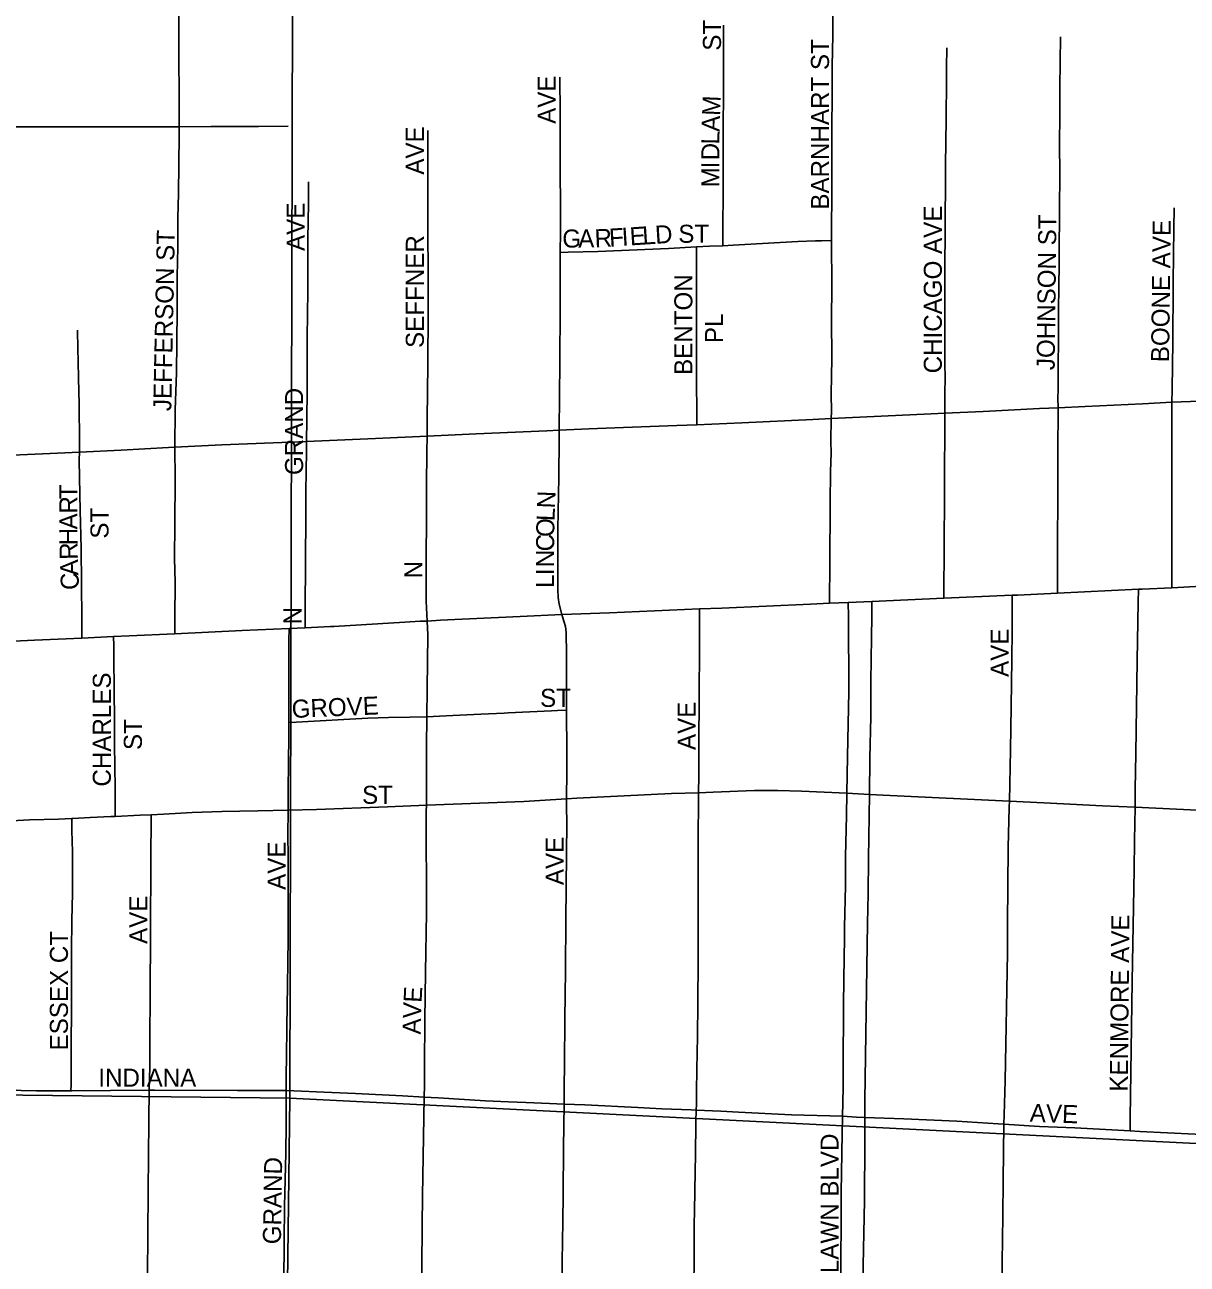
# Model space of a CAD drawing. Extents: x -9.1 to 34, y -3.1 to 22.
# Drawn here: x 6.099 to 6.709, y 19.674 to 20.324 of the extents above; entities that cross this region are included whole.
import ezdxf

# ---------------------------------------------------------------- set-up
doc = ezdxf.new("R2010")
doc.units = 0
for name, color, linetype in [('GM_X_City_Street', 7, 'Continuous'), ('GM_X_City_Street_Text', 7, 'Continuous'), ('GM_X_Section', 7, 'Continuous'), ('GM_X_State_Route', 7, 'Continuous')]:
    doc.layers.add(name, color=color, linetype=linetype)

msp = doc.modelspace()

# ---------------------------------------------------------------- linework, layer by layer
at = {"layer": 'GM_X_City_Street'}
for points in [[(6.5221, 20.21066), (6.52205, 20.22036), (6.5222, 20.23108), (6.52219, 20.23911), (6.52219, 20.24907), (6.52219, 20.25605), (6.52218, 20.26513), (6.52218, 20.27351), (6.52231, 20.2825), (6.52235, 20.30215), (6.5227, 20.31803), (6.52269, 20.32816), (6.52287, 20.34353), (6.52286, 20.36431), (6.52303, 20.3809), (6.52286, 20.40783)], [(6.17985, 20.27023), (6.17977, 20.32296), (6.17977, 20.33855)], [(6.4651, 20.20786), (6.4651, 20.21081), (6.4651, 20.22234), (6.46527, 20.23072), (6.46527, 20.24225), (6.46527, 20.25307), (6.46527, 20.26739), (6.46543, 20.29008), (6.46543, 20.30545), (6.46543, 20.3161), (6.46543, 20.32343)], [(6.64085, 20.12287), (6.64079, 20.12831), (6.64082, 20.13218), (6.64091, 20.14385), (6.64105, 20.15963), (6.64116, 20.17329), (6.64127, 20.18693), (6.64137, 20.19762), (6.64151, 20.21127), (6.64155, 20.21883), (6.64162, 20.231), (6.64169, 20.24152), (6.64166, 20.26552), (6.64171, 20.27211), (6.64177, 20.27951), (6.64185, 20.29086), (6.64196, 20.30401), (6.64206, 20.3174)], [(6.58143, 20.12008), (6.58147, 20.12574), (6.58152, 20.13183), (6.58156, 20.13736), (6.58153, 20.14712), (6.58149, 20.16142), (6.58145, 20.17277), (6.58141, 20.18625), (6.58149, 20.19909), (6.58157, 20.2129), (6.58164, 20.22408), (6.58173, 20.23822), (6.58187, 20.25269), (6.58194, 20.25943), (6.58211, 20.27686), (6.58226, 20.29215), (6.58236, 20.30119), (6.58246, 20.31153)], [(6.37977, 20.2043), (6.37981, 20.21512), (6.37975, 20.26077), (6.37968, 20.28055), (6.37956, 20.29302), (6.37959, 20.29615)], [(5.79384, 20.26928), (5.8023, 20.26936), (5.8132, 20.26947), (5.84073, 20.26965), (5.8768, 20.2699), (5.90938, 20.26984), (5.93164, 20.26984), (5.95917, 20.26985), (5.97615, 20.27011), (5.99621, 20.2702), (6.01343, 20.27006), (6.03546, 20.27004), (6.05603, 20.27005), (6.08483, 20.27013), (6.14681, 20.2701), (6.17985, 20.27023)], [(6.17766, 20.10218), (6.17786, 20.12182), (6.17844, 20.14127), (6.17883, 20.17368), (6.17882, 20.19175), (6.17916, 20.20715), (6.17927, 20.22263), (6.17947, 20.23503), (6.17983, 20.26604), (6.17985, 20.27023)], [(6.17985, 20.27023), (6.19653, 20.27029), (6.22142, 20.27037), (6.23698, 20.27056)], [(6.3099, 20.108), (6.30997, 20.11683), (6.31024, 20.14582), (6.31041, 20.17289), (6.31041, 20.19692), (6.31038, 20.21241), (6.31039, 20.24448), (6.31039, 20.25495), (6.31039, 20.26299), (6.31036, 20.26829)], [(6.24673, 20.10526), (6.24687, 20.11647), (6.24703, 20.13219), (6.24703, 20.14511), (6.24703, 20.15978), (6.24718, 20.17193), (6.24738, 20.1841), (6.24737, 20.19854), (6.24736, 20.21146), (6.24771, 20.22997), (6.24771, 20.24132)], [(6.7006, 20.12573), (6.70062, 20.13208), (6.70086, 20.14559), (6.70108, 20.15697), (6.70101, 20.1663), (6.70115, 20.17781), (6.70127, 20.18834), (6.70144, 20.20329), (6.70159, 20.21661), (6.70172, 20.22769)], [(6.37977, 20.2043), (6.384, 20.2044), (6.39939, 20.20473), (6.4365, 20.20643), (6.45114, 20.20718)], [(6.45114, 20.20718), (6.45811, 20.20753), (6.4651, 20.20786)], [(6.45135, 20.11396), (6.45133, 20.11687), (6.45115, 20.14027), (6.45115, 20.16156), (6.45114, 20.18514), (6.45114, 20.19614), (6.45114, 20.20365), (6.45114, 20.20718)], [(6.4651, 20.20786), (6.47041, 20.20811), (6.48577, 20.20908), (6.50434, 20.21007), (6.51361, 20.21041), (6.51669, 20.21049), (6.5221, 20.21066)], [(6.5219, 20.11722), (6.52195, 20.12084), (6.52192, 20.13017), (6.52212, 20.14875), (6.52203, 20.16945), (6.5222, 20.18603), (6.5221, 20.21066)], [(6.37923, 20.11116), (6.37957, 20.14679), (6.37966, 20.17468), (6.37977, 20.2043)], [(6.12754, 20.09957), (6.12761, 20.10478), (6.12737, 20.12475), (6.12717, 20.13831), (6.12697, 20.14714), (6.12677, 20.15382), (6.12658, 20.16364)], [(6.7006, 20.12573), (6.71033, 20.12622), (6.73339, 20.12754), (6.75525, 20.12831)], [(6.5219, 20.11722), (6.57433, 20.11975), (6.58143, 20.12008)], [(6.58091, 20.023), (6.58095, 20.0307), (6.58104, 20.04402), (6.58113, 20.05849), (6.5812, 20.06901), (6.58129, 20.08513), (6.58137, 20.09713), (6.5814, 20.10274), (6.58138, 20.11328), (6.58143, 20.12008)], [(6.58143, 20.12008), (6.60162, 20.12092), (6.6311, 20.12241), (6.64085, 20.12287)], [(6.6405, 20.02568), (6.64053, 20.03335), (6.64055, 20.04059), (6.6406, 20.05357), (6.64067, 20.0743), (6.64072, 20.08695), (6.64077, 20.10224), (6.64083, 20.12), (6.64085, 20.12287)], [(6.64085, 20.12287), (6.65504, 20.12355), (6.68513, 20.12489), (6.7006, 20.12573)], [(6.70049, 20.02852), (6.70049, 20.03737), (6.7005, 20.04758), (6.70052, 20.05958), (6.70053, 20.06747), (6.70055, 20.08441), (6.70058, 20.10546), (6.70059, 20.11697), (6.7006, 20.12573)], [(6.37923, 20.11116), (6.39475, 20.11181), (6.41287, 20.11248), (6.44086, 20.11353), (6.45135, 20.11396)], [(6.45135, 20.11396), (6.47503, 20.11493), (6.51229, 20.11678), (6.5219, 20.11722)], [(6.52095, 20.02037), (6.52102, 20.02836), (6.52107, 20.03415), (6.52123, 20.04033), (6.52136, 20.07306), (6.52153, 20.08948), (6.52178, 20.09913), (6.52174, 20.10535), (6.5219, 20.11722)], [(6.24673, 20.10526), (6.28288, 20.10676), (6.3099, 20.108)], [(6.31001, 20.01103), (6.3094, 20.02139), (6.3094, 20.03896), (6.30955, 20.06996), (6.30965, 20.08222), (6.30984, 20.09954), (6.3099, 20.108)], [(6.3099, 20.108), (6.3356, 20.10919), (6.37268, 20.11071), (6.37923, 20.11116)], [(6.38055, 20.01441), (6.37923, 20.01996), (6.37867, 20.02343), (6.37843, 20.02759), (6.37854, 20.03548), (6.37854, 20.04701), (6.37854, 20.05923), (6.37905, 20.08647), (6.37918, 20.10651), (6.37923, 20.11116)], [(6.12754, 20.09957), (6.14952, 20.10059), (6.17433, 20.10199), (6.17766, 20.10218)], [(6.17765, 20.00442), (6.17768, 20.01261), (6.17776, 20.03127), (6.17748, 20.04403), (6.17767, 20.06191), (6.17786, 20.08548), (6.17766, 20.10218)], [(6.17766, 20.10218), (6.20226, 20.10336), (6.24259, 20.10508), (6.24673, 20.10526)], [(6.24602, 20.00756), (6.24602, 20.01747), (6.24602, 20.02567), (6.24618, 20.03353), (6.24618, 20.03929), (6.24617, 20.04479), (6.24618, 20.05117), (6.24638, 20.05724), (6.24635, 20.06811), (6.24635, 20.07684), (6.24652, 20.0915), (6.24669, 20.09814), (6.24673, 20.10526)], [(6.05562, 20.09643), (6.0596, 20.0965), (6.06269, 20.09655), (6.06579, 20.09668), (6.08435, 20.09775), (6.11227, 20.09887), (6.12754, 20.09957)], [(6.12891, 20.00214), (6.12881, 20.01213), (6.12845, 20.04924), (6.12797, 20.06897), (6.12771, 20.08623), (6.12748, 20.0955), (6.12754, 20.09957)], [(6.61535, 19.91666), (6.61593, 19.94352), (6.61631, 19.96623), (6.61668, 19.99092), (6.61673, 20.00624), (6.61672, 20.01777), (6.61671, 20.02457)], [(6.68123, 19.91343), (6.68125, 19.91459), (6.68127, 19.92291), (6.68159, 19.94135), (6.68238, 19.9906), (6.68286, 20.0207), (6.68298, 20.02768)], [(6.45229, 19.92105), (6.45237, 19.92984), (6.45252, 19.94876), (6.45269, 19.96885), (6.45272, 19.99994), (6.45272, 20.00925), (6.45272, 20.01738)], [(6.53014, 19.92074), (6.53044, 19.94001), (6.53103, 19.9741), (6.53085, 20.01336), (6.53082, 20.0208)], [(6.54193, 19.92017), (6.54217, 19.93917), (6.5426, 19.96083), (6.5427, 19.9794), (6.54298, 20.00234), (6.54312, 20.01343), (6.54322, 20.02135)], [(6.30973, 19.96086), (6.30994, 19.97557), (6.31035, 20.00386), (6.31001, 20.01103)], [(6.3831, 19.96436), (6.38304, 19.99372), (6.38283, 20.00497), (6.38243, 20.00816), (6.3817, 20.01102), (6.38055, 20.01441)], [(6.23744, 19.95779), (6.23745, 19.96533), (6.23747, 19.97634), (6.23748, 19.9867), (6.2375, 20.00084), (6.23752, 20.00719)], [(6.1464, 19.90859), (6.14637, 19.91222), (6.14625, 19.92395), (6.14616, 19.93451), (6.14604, 19.94664), (6.14591, 19.96072), (6.1458, 19.97298), (6.14573, 19.98054), (6.14568, 19.98615), (6.14557, 19.99815), (6.14552, 20.00289)], [(6.30973, 19.96086), (6.31635, 19.96119), (6.32344, 19.96153), (6.33804, 19.96224), (6.35041, 19.9628), (6.35238, 19.96288), (6.37519, 19.96391), (6.37828, 19.96408), (6.3831, 19.96436)], [(6.38309, 19.91781), (6.3831, 19.92351), (6.38315, 19.9266), (6.38317, 19.9297), (6.38314, 19.94207), (6.3831, 19.96436)], [(6.23707, 19.91193), (6.23714, 19.92076), (6.23728, 19.93819), (6.23737, 19.94937), (6.23743, 19.95724), (6.23744, 19.95779)], [(6.23744, 19.95779), (6.24121, 19.95801), (6.27886, 19.96015), (6.28972, 19.96049), (6.3009, 19.96072), (6.30973, 19.96086)], [(6.30953, 19.91449), (6.3096, 19.93036), (6.30966, 19.94532), (6.30973, 19.96086)], [(6.38309, 19.91781), (6.38851, 19.9181), (6.43817, 19.92059), (6.45229, 19.92105)], [(6.45106, 19.7546), (6.45114, 19.75774), (6.45124, 19.76436), (6.45141, 19.77586), (6.45167, 19.79346), (6.45193, 19.81055), (6.45207, 19.83348), (6.45212, 19.84141), (6.45206, 19.86317), (6.45206, 19.89334), (6.45229, 19.92105)], [(6.45229, 19.92105), (6.4599, 19.92127), (6.48157, 19.92212), (6.48755, 19.92222), (6.49391, 19.92222), (6.50629, 19.92185), (6.53014, 19.92074)], [(6.52779, 19.75141), (6.52788, 19.75865), (6.52808, 19.76683), (6.52806, 19.77612), (6.52827, 19.81024), (6.52868, 19.83504), (6.52892, 19.8443), (6.52889, 19.85047), (6.52934, 19.87215), (6.52936, 19.88454), (6.52945, 19.88759), (6.52997, 19.90909), (6.53014, 19.92074)], [(6.53014, 19.92074), (6.54193, 19.92017)], [(6.53954, 19.75075), (6.53958, 19.75973), (6.54094, 19.85257), (6.54127, 19.86802), (6.5415, 19.88658), (6.54193, 19.92017)], [(6.54193, 19.92017), (6.55272, 19.91963), (6.61535, 19.91666)], [(6.23707, 19.91193), (6.25198, 19.91218), (6.2892, 19.91365), (6.30953, 19.91449)], [(6.3084, 19.76145), (6.30849, 19.76757), (6.30863, 19.77786), (6.30867, 19.80193), (6.30902, 19.82692), (6.30962, 19.85813), (6.30952, 19.91114), (6.30953, 19.91449)], [(6.30953, 19.91449), (6.3606, 19.9165), (6.38309, 19.91781)], [(6.38183, 19.75778), (6.3819, 19.76319), (6.38205, 19.78226), (6.38218, 19.79903), (6.38233, 19.81842), (6.38253, 19.82454), (6.38274, 19.85806), (6.3828, 19.86775), (6.38305, 19.89243), (6.38315, 19.90182), (6.38309, 19.91732), (6.38309, 19.91781)], [(6.61244, 19.74731), (6.61256, 19.75214), (6.61302, 19.76998), (6.61429, 19.83702), (6.61428, 19.85222), (6.61463, 19.89228), (6.61528, 19.91347), (6.61535, 19.91666)], [(6.61535, 19.91666), (6.63331, 19.91578), (6.66423, 19.91419), (6.68123, 19.91343)], [(6.67858, 19.74374), (6.67866, 19.75039), (6.67964, 19.82217), (6.68079, 19.88068), (6.68096, 19.89593), (6.68123, 19.91343)], [(6.68123, 19.91343), (6.7138, 19.9119), (6.73122, 19.91113), (6.74481, 19.91096), (6.74678, 19.91091)], [(6.08929, 19.90612), (6.09516, 19.90642), (6.10136, 19.90675), (6.11656, 19.90721), (6.12353, 19.90753)], [(6.12311, 19.76467), (6.12321, 19.76813), (6.1232, 19.78934), (6.12336, 19.8071), (6.12336, 19.81631), (6.12336, 19.83834), (6.12362, 19.85396), (6.12388, 19.8684), (6.12391, 19.88997), (6.12367, 19.90116), (6.12353, 19.90753)], [(6.12353, 19.90753), (6.12412, 19.90756), (6.13326, 19.90799), (6.14404, 19.90848), (6.1464, 19.90859)], [(6.1464, 19.90859), (6.15946, 19.9092), (6.16529, 19.90948)], [(6.16417, 19.76506), (6.16426, 19.77123), (6.16445, 19.77738), (6.16457, 19.79823), (6.16463, 19.80875), (6.16472, 19.82454), (6.1648, 19.83803), (6.16493, 19.86203), (6.16499, 19.87157), (6.1651, 19.89101), (6.16523, 19.90341), (6.16529, 19.90948)], [(6.16529, 19.90948), (6.17174, 19.9098), (6.18078, 19.91039), (6.18675, 19.91069), (6.20225, 19.9112), (6.22119, 19.91161), (6.23707, 19.91193)], [(6.23594, 19.76488), (6.23603, 19.77228), (6.23616, 19.78329), (6.23633, 19.79727), (6.23656, 19.81042), (6.2367, 19.81897), (6.23694, 19.83328), (6.23711, 19.84314), (6.23706, 19.86288), (6.23704, 19.87423), (6.237, 19.88771), (6.23697, 19.89861), (6.23707, 19.91193)], [(6.08823, 19.76563), (6.09121, 19.76529), (6.09446, 19.76502), (6.09696, 19.76481), (6.10506, 19.76465), (6.12311, 19.76467)], [(6.12311, 19.76467), (6.12364, 19.76467), (6.16417, 19.76506)], [(6.16242, 19.54826), (6.16199, 19.55458), (6.16193, 19.5558), (6.16192, 19.55698), (6.16207, 19.56407), (6.16226, 19.57953), (6.16238, 19.58956), (6.16248, 19.59828), (6.16255, 19.60452), (6.16266, 19.61373), (6.16276, 19.62261), (6.16291, 19.6352), (6.16304, 19.64859), (6.16324, 19.66915), (6.16343, 19.68872), (6.16367, 19.71289), (6.16383, 19.72999), (6.16402, 19.74959), (6.16417, 19.76506)], [(6.16417, 19.76506), (6.16704, 19.76499), (6.21046, 19.76493), (6.22286, 19.76495), (6.23523, 19.76491), (6.23594, 19.76488)], [(6.23449, 19.64157), (6.23478, 19.65805), (6.23479, 19.66424), (6.23498, 19.68576), (6.23521, 19.70433), (6.23581, 19.73206), (6.23595, 19.74728), (6.23597, 19.76159), (6.23594, 19.76488)], [(6.23594, 19.76488), (6.25997, 19.76391), (6.27235, 19.76335), (6.29711, 19.76215), (6.3084, 19.76145)], [(6.30681, 19.63638), (6.30685, 19.64068), (6.30719, 19.67229), (6.30733, 19.69405), (6.30749, 19.70959), (6.30811, 19.74064), (6.3084, 19.76145)], [(6.3084, 19.76145), (6.31572, 19.76099), (6.3405, 19.75951), (6.3527, 19.75896), (6.36179, 19.75852), (6.3741, 19.75806), (6.38183, 19.75778)], [(6.37683, 19.41986), (6.37696, 19.42225), (6.37756, 19.43282), (6.37771, 19.43498), (6.37775, 19.43845), (6.37829, 19.49072), (6.37873, 19.50781), (6.37899, 19.52114), (6.37931, 19.53758), (6.37987, 19.5738), (6.38007, 19.58741), (6.38024, 19.59875), (6.38034, 19.62045), (6.38045, 19.63772), (6.38057, 19.65741), (6.38079, 19.67521), (6.38106, 19.69625), (6.38123, 19.7104), (6.38154, 19.73507), (6.38183, 19.75778)], [(6.38183, 19.75778), (6.39268, 19.75738), (6.42053, 19.75597), (6.43296, 19.75529), (6.4485, 19.7547), (6.45106, 19.7546)], [(6.44723, 19.40568), (6.44725, 19.41237), (6.44727, 19.42388), (6.44728, 19.43358), (6.4473, 19.44542), (6.44741, 19.45545), (6.44772, 19.4845), (6.44784, 19.49607), (6.448, 19.51087), (6.4482, 19.52829), (6.44845, 19.55165), (6.44873, 19.57746), (6.44886, 19.59703), (6.44901, 19.61002), (6.44918, 19.62465), (6.44935, 19.63979), (6.44999, 19.67386), (6.44993, 19.68629), (6.45005, 19.69388), (6.45033, 19.71131), (6.45052, 19.72331), (6.45063, 19.73022), (6.45092, 19.74857), (6.45106, 19.7546)], [(6.45106, 19.7546), (6.46399, 19.75407), (6.47323, 19.75351), (6.50098, 19.75222), (6.52779, 19.75141)], [(6.52515, 19.51595), (6.52523, 19.52482), (6.52533, 19.53518), (6.52533, 19.54445), (6.52588, 19.55982), (6.52588, 19.56774), (6.5261, 19.58501), (6.5263, 19.60128), (6.5265, 19.61658), (6.52655, 19.62052), (6.52672, 19.63405), (6.5268, 19.64716), (6.52694, 19.66722), (6.527, 19.67738), (6.52701, 19.69468), (6.52702, 19.70209), (6.52704, 19.71135), (6.52764, 19.74235), (6.52779, 19.75141)], [(6.52779, 19.75141), (6.53512, 19.75091), (6.53954, 19.75075)], [(6.53628, 19.5166), (6.53712, 19.56792), (6.53743, 19.61125), (6.53861, 19.67318), (6.53927, 19.70715), (6.53949, 19.73807), (6.53954, 19.75075)], [(6.53954, 19.75075), (6.55995, 19.75001), (6.58778, 19.7488), (6.60945, 19.7475), (6.61244, 19.74731)], [(6.61008, 19.51918), (6.61083, 19.5784), (6.61114, 19.6405), (6.6116, 19.67463), (6.61174, 19.68696), (6.61183, 19.69922), (6.61209, 19.71775), (6.61244, 19.74731)], [(6.61244, 19.74731), (6.63111, 19.7461), (6.64969, 19.74525), (6.67858, 19.74374)], [(6.67858, 19.74374), (6.68381, 19.74347), (6.72726, 19.74125), (6.74547, 19.74022)]]:
    msp.add_lwpolyline(points, dxfattribs=at)
at = {"layer": 'GM_X_Section'}
for points in [[(5.2279, 20.77322), (6.2403, 20.76479), (6.2379, 19.76083), (5.226, 19.77229)], [(7.2498, 20.73584), (7.24082, 19.71069), (6.2379, 19.76083), (6.2403, 20.76479)], [(5.226, 19.77229), (6.2379, 19.76083), (6.22532, 18.76489), (5.22068, 18.771)], [(6.2379, 19.76083), (7.24082, 19.71069), (7.22846, 18.75339), (6.22532, 18.76489)]]:
    msp.add_lwpolyline(points, close=True, dxfattribs=at)
at = {"layer": 'GM_X_State_Route'}
for points in [[(6.26102, 20.00824), (6.29829, 20.01043), (6.30631, 20.0109), (6.31001, 20.01103), (6.31704, 20.01143), (6.35876, 20.01337), (6.38055, 20.01441), (6.40553, 20.01536), (6.45272, 20.01738), (6.46449, 20.01788), (6.511, 20.01994), (6.52095, 20.02037), (6.53082, 20.0208), (6.54322, 20.02135), (6.58091, 20.023), (6.61671, 20.02457), (6.61962, 20.0247), (6.6405, 20.02568), (6.68298, 20.02768), (6.68498, 20.02777), (6.70049, 20.02852), (6.71608, 20.02927)], [(5.91225, 19.9936), (5.91711, 19.99365), (5.93047, 19.9938), (5.95611, 19.99482), (5.97225, 19.99547), (6.05437, 19.99875), (6.05587, 19.99882), (6.10406, 20.001), (6.12891, 20.00214), (6.14552, 20.00289), (6.15376, 20.00327), (6.17765, 20.00442), (6.21289, 20.00612), (6.23752, 20.00719), (6.24602, 20.00756), (6.25934, 20.00814), (6.26102, 20.00824)]]:
    msp.add_lwpolyline(points, dxfattribs=at)

# ---------------------------------------------------------------- texts
at = {"layer": 'GM_X_City_Street_Text'}
for s, height, rotation, p in [('ST', 0.00947, 90, (6.46406, 20.31009)), ('BARNHART ST', 0.0094697, 90, (6.52073, 20.22676)), ('AVE', 0.00947, 90, (6.37739, 20.27175)), ('M', 0.00947, 87.61329, (6.46357, 20.27582)), ('A', 0.00947, 88.03258, (6.46328, 20.26751)), ('AVE', 0.00947, 90, (6.30823, 20.24509)), ('L', 0.00947, 89.59016, (6.46324, 20.26091)), ('D', 0.00947, 89.98125, (6.46323, 20.25259)), ('I', 0.00947, 89.95628, (6.46323, 20.24842)), ('M', 0.00947, 89.98178, (6.46323, 20.23842)), ('AVE', 0.00947, 90, (6.24573, 20.20509)), ('CHICAGO AVE', 0.0094697, 90, (6.57989, 20.14092)), ('JOHNSON ST', 0.00947, 89.3192, (6.63906, 20.14256)), ('E', 0.00947, 3.65514, (6.41646, 20.20797)), ('L', 0.00947, 3.63598, (6.42311, 20.2084)), ('D', 0.00947, 3.64791, (6.42977, 20.20882)), ('ST', 0.00947, 0.00001, (6.44168, 20.20937)), ('BOONE AVE', 0.00947, 89.29137, (6.69906, 20.14672)), ('JEFFERSON ST', 0.0094697, 88.81911, (6.17573, 20.12105)), ('SEFFNER', 0.00947, 90, (6.30823, 20.15425)), ('G', 0.00947, 0.04372, (6.38084, 20.20687)), ('A', 0.00947, 0.31953, (6.38923, 20.20688)), ('R', 0.00947, 2.62979, (6.39797, 20.20694)), ('F', 0.00947, 3.63011, (6.40565, 20.20729)), ('I', 0.00947, 3.64239, (6.4123, 20.20771)), ('BENTON', 0.00947, 90, (6.44906, 20.14009)), ('PL', 0.00947, 90, (6.46517, 20.15676)), ('GRAND', 0.00947, 90, (6.24489, 20.08759)), ('T', 0.00947, 90, (6.12656, 20.07491)), ('R', 0.00947, 90, (6.12656, 20.06741)), ('N', 0.00947, 87.70414, (6.37699, 20.06998)), ('ST', 0.00947, 90, (6.14285, 20.05426)), ('L', 0.00947, 87.7869, (6.37673, 20.06332)), ('A', 0.00947, 90, (6.12656, 20.05907)), ('O', 0.00947, 88.88525, (6.37657, 20.05504)), ('H', 0.00947, 90.21861, (6.12659, 20.05075)), ('C', 0.00947, 89.9757, (6.37657, 20.04758)), ('R', 0.00947, 91.55473, (6.12679, 20.04331)), ('A', 0.00947, 92.18581, (6.12711, 20.03501)), ('N', 0.00947, 89.97813, (6.37656, 20.03925)), ('C', 0.00947, 92.18581, (6.1274, 20.02752)), ('N', 0.00947, 90, (6.3074, 20.03342)), ('I', 0.00947, 89.98499, (6.37656, 20.03509)), ('L', 0.00947, 89.97267, (6.37656, 20.02842)), ('N', 0.00947, 90, (6.24406, 20.00925)), ('AVE', 0.00947, 90, (6.61489, 19.98175)), ('CHARLES', 0.00947, 90, (6.14406, 19.92425)), ('GROVE', 0.00947, 2.38916, (6.2391, 19.9602)), ('ST', 0.00947, 0.00001, (6.36918, 19.96604)), ('AVE', 0.00947, 90, (6.45073, 19.94342)), ('ST', 0.00947, 90, (6.16035, 19.94342)), ('ST', 0.00947, 0.00001, (6.27584, 19.9152)), ('AVE', 0.00947, 90, (6.23573, 19.87009)), ('AVE', 0.00947, 90, (6.38156, 19.87259)), ('AVE', 0.00947, 90, (6.16323, 19.84175)), ('KENMORE AVE', 0.0094697, 89.43302, (6.67739, 19.76427)), ('ESSEX CT', 0.00947, 90, (6.12156, 19.78592)), ('E', 0.00947, 87.15804, (6.30701, 19.81079)), ('V', 0.00947, 87.50759, (6.30665, 19.80248)), ('A', 0.00947, 89.36607, (6.30656, 19.79423)), ('INDIANA', 0.00947, 0.00001, (6.13751, 19.76687)), ('AVE', 0.00947, 358.02636, (6.6259, 19.74854)), ('FOREST LAWN BLVD', 0.0094697, 90, (6.52573, 19.61426)), ('GRAND', 0.00947, 89.02815, (6.23323, 19.68421))]:
    msp.add_text(s, height=height, rotation=rotation, dxfattribs=at).set_placement(p)

doc.saveas('drawing.dxf')
